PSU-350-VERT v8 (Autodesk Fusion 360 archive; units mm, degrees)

design "PSU-350-VERT" references "MW-LRS-350", "486-1965-ND"
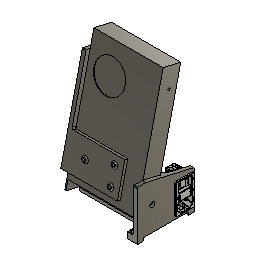
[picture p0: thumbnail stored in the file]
sketch "Sketch3" plane through (0, 0, 0) normal (1, 0, 0) x axis (0, 1, 0)
  line L1 (30.2311, 6) -> (1, 12.7485)
  line L2 (78.5956, 215.4896) -> (30.2311, 6)
  line L3 (49.3645, 222.2381) -> (78.5956, 215.4896)
  line L4 (1, 12.7485) -> (49.3645, 222.2381)
  line L5 (95, 0) -> (0, 0)
  line L6 (25.3624, 40.4789) -> (59.105, 186.6344)
  line L7 (54.4133, 110.7448) -> (42.2337, 113.5567)
  line L8 (91.75, 6) -> (63.75, 6)
  line L9 (91.75, 52.9) -> (91.75, 6)
  line L10 (63.75, 52.9) -> (91.75, 52.9)
  line L11 (63.75, 6) -> (63.75, 52.9)
  line L12 (93, 54.15) -> (93, 4.75)
  line L13 (62.5, 54.15) -> (93, 54.15)
  line L14 (62.5, 4.75) -> (62.5, 54.15)
  line L15 (93, 4.75) -> (62.5, 4.75)
  line L16 (30.2311, 6) -> (63.75, 6)
  line L17 (24.9093, 5.176) -> (25.3593, 7.1248)
  line L18 (0, 0) -> (0, 12.8625)
  line L19 (95, 58.8198) -> (45.0859, 70.3434)
  line L20 (95, 0) -> (95, 58.8198)
  line L21 (36.3889, 6) -> (50.9322, 68.9936)
  line L22 (14.8805, 77.3168) -> (0, 12.8625)
  line L23 (45.0859, 70.3434) -> (14.8805, 77.3168)
  line L24 (61.75, 4) -> (61.75, 6)
  line L25 (95, 4) -> (61.75, 4)
  line L26 (35.0037, 0) -> (36.3889, 6)
  line L27 (48.3889, 0) -> (48.3889, 6)
  line L28 (24.9093, 0) -> (24.9093, 5.176)
  line L29 (35.0037, -5) -> (35.0037, 0)
  line L30 (48.3889, -5) -> (35.0037, -5)
  line L31 (48.3889, 0) -> (48.3889, -5)
  line L32 (0, -5) -> (0, 0)
  line L33 (10, -5) -> (0, -5)
  line L34 (10, 0) -> (10, -5)
  line L35 (95, -5) -> (95, 0)
  line L36 (85, -5) -> (95, -5)
  line L37 (85, 0) -> (85, -5)
  line L38 (10, 6) -> (10, 0)
  line L39 (0, 6) -> (10, 6)
  line L40 (94, 55.15) -> (94, 4)
  line L41 (61.75, 55.15) -> (94, 55.15)
  line L42 (61.75, 6) -> (61.75, 55.15)
  line L43 (85, 4) -> (85, 0)
  line L44 (0, 77.3168) -> (0, 12.8625)
  line L45 (14.8805, 77.3168) -> (0, 77.3168)
  circle C1 centre (25.3624, 40.4789) radius 2.125
  circle C2 centre (59.105, 186.6344) radius 2.125
  point P1 (0, 0)
  point P6 (0, 0)
  point P9 (59.105, 186.6344)
  point P10 (59.105, 186.6344)
  point P8 (25.3624, 40.4789)
  point P11 (25.3624, 40.4789)
  point P12 (42.2337, 113.5567)
  point P13 (54.4133, 110.7448)
  point P3 (30.2311, 6)
  point P22 (25.3593, 7.1248)
  point P24 (0, 0)
  point P25 (45.0859, 70.3434)
  point P27 (50.9322, 68.9936)
  point P28 (36.3889, 6)
  point P31 (45.0859, 70.3434)
  point P32 (61.75, 6)
  point P34 (95, 4)
  point P35 (35.0037, 0)
  point P36 (48.3889, 6)
  point P37 (48.3889, 0)
  point P38 (24.9093, 0)
  point P41 (48.3889, 0)
  point P44 (10, 0)
  point P47 (85, 0)
  point P40 (48.3889, -5)
  point P39 (35.0037, -5)
  point P49 (0, 6)
  point P50 (94, 4)
  point P53 (61.75, 6)
  point P54 (85, 4)
  point P30 (14.8805, 77.3168)
  point P56 (14.8805, 77.3168)
  point P4 (78.5956, 215.4896)
  point P5 (49.3645, 222.2381)
  point P2 (1, 12.7485)
  point P7 (95, 0)
  point P16 (91.75, 52.9)
  point P17 (63.75, 52.9)
  point P15 (91.75, 6)
  point P19 (93, 54.15)
  point P14 (63.75, 6)
  point P23 (24.9093, 5.176)
  point P42 (0, -5)
  point P43 (10, -5)
  point P45 (95, -5)
  point P46 (85, -5)
  perpendicular L1 L2
  parallel L1 L3
  parallel L2 L4
  coincident P1 P6
  horizontal L5
  coincident P9 P10
  coincident P8 P11
  parallel L2 L6
  equal C1 C2
  midpoint L6 P12
  coincident L2 P13
  perpendicular L2 L7
  midpoint L2 P13
  perpendicular L8 L9
  parallel L8 L10
  parallel L9 L11
  horizontal L8
  coincident P3 L8
  coincident L1 P22
  perpendicular L1 L17
  coincident L5 P24
  perpendicular L5 L18
  coincident P1 P24
  coincident L2 P25
  perpendicular L2 L19
  vertical L20
  coincident L19 P27
  coincident L16 P28
  perpendicular L19 L21
  parallel L4 L22
  perpendicular L6 L23
  coincident P25 P31
  coincident L16 P32
  perpendicular L16 L24
  coincident L20 P34
  perpendicular L24 L25
  coincident L5 P35
  parallel L21 L26
  coincident L16 P36
  coincident L5 P37
  perpendicular L5 L27
  coincident L5 P38
  perpendicular L5 L28
  perpendicular L5 L29
  perpendicular L29 L30
  perpendicular L30 L31
  coincident P37 P41
  perpendicular L5 L32
  perpendicular L32 L33
  coincident L5 P44
  perpendicular L5 L34
  perpendicular L5 L35
  coincident L5 P47
  perpendicular L5 L37
  coincident P40 L36
  coincident P39 L33
  horizontal L36
  perpendicular L5 L38
  coincident L18 P49
  perpendicular L18 L39
  coincident P28 L39
  coincident L25 P50
  perpendicular L13 L40
  perpendicular L12 L41
  perpendicular L41 L42
  coincident P32 P53
  coincident L25 P54
  perpendicular L25 L43
  parallel L18 L44
  perpendicular L44 L45
  coincident P30 P56
  dimension "d3" distance P4 P5 = 30
  dimension "d4" distance P2 P5 = 215
  dimension "d5" distance P6 P7 = 95
  dimension "d6" angle L2 L5 = 77
  dimension "d7" diameter C2 = 4.25
  dimension "d8" distance L2 L6 = 12.5
  dimension "d9" distance P10 P11 = 150
  dimension "d10" distance P16 P17 = 28
  dimension "d11" distance P15 P16 = 46.9
  dimension "d12" = 1.25
  dimension "d13" = 30
  dimension "d15" distance P7 P15 = 6
  dimension "d16" distance P7 L12 = 2
  dimension "d17" distance P3 L17 = 5
  dimension "d18" distance P19 L19 = 5
  dimension "d19" distance P25 L21 = 6
  dimension "d20" distance P2 L18 = 1
  dimension "d21" distance L4 L22 = 1
  dimension "d22" distance P15 L25 = 2
  dimension "d23" distance P14 L24 = 2
  dimension "d31" distance P28 L27 = 12
  dimension "d32" distance L1 P23 = 2
  dimension "d33" distance P36 L30 = 11
  dimension "d34" distance P42 P43 = 10
  dimension "d35" distance P45 P46 = 10
  dimension "d72" distance P19 L41 = 1
  dimension "d73" distance L12 L40 = 1
extrude "Extrude1" new body sketch "Sketch3" profile of L1 L2 L4 L5 C1 L8 L9 L10 L11 L16 L17 L18 L19 L20 L21 L22 L23 L24 L25 against normal blind 2
extrude "Extrude2" add sketch "Sketch3" profile of L1 L2 L4 L5 C1 L16 L17 L18 L19 L20 L21 L22 L23 L24 L25 L26 L27 L28 L32 L33 L34 L35 L36 L37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 against normal blind 6
extrude "Extrude3" sketch "Sketch3" profile of L1 L2 L5 L16 L17 L19 L21 L26 L28 blind -10
extrude "Extrude4" sketch "Sketch3" profile of L1 L2 L5 L16 L17 L19 L21 L26 L27 L28 blind -115
extrude "Extrude5" add sketch "Sketch3" profile of L5 L20 L25 L35 L36 L37 L43 against normal blind 10
extrude "Extrude6" sketch "Sketch3" profile of L5 L29 L30 L31 blind 10
chamfer "Chamfer1" distance 5
extrude "Extrude7" sketch "Sketch3" profile of L5 L18 L32 L33 L34 L38 L39 blind -10
sketch "Sketch4" plane through (0, 0, -5) normal (0, 0, -1) x axis (1, 0, 0)
  line L1 (-121, -48.3889) -> (-121, -35.0037)
  line L2 (-111, -48.3889) -> (-121, -48.3889)
  line L3 (-111, -35.0037) -> (-111, -48.3889)
  line L4 (-121, -35.0037) -> (-111, -35.0037)
  line L5 (-120.0415, -41.6963) -> (-118.0207, -38.1963)
  line L6 (-118.0207, -45.1963) -> (-120.0415, -41.6963)
  line L7 (-113.9793, -45.1963) -> (-118.0207, -45.1963)
  line L8 (-111.9585, -41.6963) -> (-113.9793, -45.1963)
  line L9 (-113.9793, -38.1963) -> (-111.9585, -41.6963)
  line L10 (-118.0207, -38.1963) -> (-113.9793, -38.1963)
  line L11 (-9.0415, -90) -> (-7.0207, -86.5)
  line L12 (-7.0207, -86.5) -> (-2.9793, -86.5)
  line L13 (-7.0207, -93.5) -> (-9.0415, -90)
  line L14 (-0.9585, -90) -> (-2.9793, -93.5)
  line L15 (-2.9793, -86.5) -> (-0.9585, -90)
  line L16 (-2.9793, -93.5) -> (-7.0207, -93.5)
  line L17 (-15.0415, -5) -> (-13.0207, -1.5)
  line L18 (-13.0207, -1.5) -> (-8.9793, -1.5)
  line L19 (-13.0207, -8.5) -> (-15.0415, -5)
  line L20 (-6.9585, -5) -> (-8.9793, -8.5)
  line L21 (-8.9793, -1.5) -> (-6.9585, -5)
  line L22 (-8.9793, -8.5) -> (-13.0207, -8.5)
  line L23 (-16, 0) -> (0, 0)
  line L24 (-16, -10) -> (-16, 0)
  line L25 (0, -10) -> (-16, -10)
  line L26 (0, -85) -> (0, -95)
  line L27 (-10, -85) -> (0, -85)
  line L28 (-10, -95) -> (-10, -85)
  line L29 (0, -95) -> (-10, -95)
  line L30 (-111, -35.0037) -> (-121, -48.3889)
  line L31 (-16, 0) -> (-6, -10)
  line L32 (0, -85) -> (-10, -95)
  line L33 (0, 0) -> (0, -10)
  line L34 (-6, 0) -> (-6, -10)
  circle C1 centre (-116, -41.6963) radius 2.25
  circle C2 centre (-5, -90) radius 2.25
  circle C3 centre (-11, -5) radius 2.25
  point P6 (-116, -41.6963)
  point P13 (-116, -41.6963)
  point P14 (-5, -90)
  point P18 (-5, -90)
  point P22 (-11, -5)
  point P26 (-11, -5)
  point P3 (-121, -48.3889)
  point P38 (-121, -48.3889)
  point P5 (-111, -35.0037)
  point P39 (-111, -35.0037)
  point P32 (-16, 0)
  point P40 (-16, 0)
  point P37 (-10, -95)
  point P41 (-10, -95)
  point P35 (0, -85)
  point P42 (0, -85)
  point P43 (-6, -10)
  point P45 (-6, -10)
  point P9 (-118.0207, -45.1963)
  point P21 (-7.0207, -93.5)
  point P29 (-13.0207, -8.5)
  coincident P6 P13
  horizontal L10
  coincident P14 P18
  horizontal L12
  coincident P22 P26
  horizontal L18
  coincident P3 P38
  coincident P5 P39
  midpoint P6 L30
  coincident P32 P40
  midpoint P26 L31
  coincident P37 P41
  coincident P35 P42
  midpoint P14 L32
  coincident P43 P45
  dimension "d49" distance P9 L10 = 7
  dimension "d50" diameter C1 = 4.5
  dimension "d51" distance P21 L12 = 7
  dimension "d52" diameter C2 = 4.5
  dimension "d53" distance P29 L18 = 7
  dimension "d54" diameter C3 = 4.5
extrude "Extrude8" cut sketch "Sketch4" profile of C1 C2 C3 against normal blind 12
extrude "Extrude9" cut sketch "Sketch4" profile of C1 L5 L6 L7 L8 L9 L10 C2 L11 L12 L13 L14 L15 L16 C3 L17 L18 L19 L20 L21 L22 blind -12 from offset -3
extrude "Extrude10" cut sketch "Sketch3" profile of C1 to an object
sketch "Sketch5" plane through (0, 27.3862, -6.3226) normal (0, -0.9744, 0.225) x axis (1, 0, 0)
  line L1 (-6, 78.6826) -> (-6, 12.6467)
  line L2 (-121, 78.6826) -> (-6, 78.6826)
  line L3 (-121, 12.6467) -> (-121, 78.6826)
  line L4 (-6, 12.6467) -> (-121, 12.6467)
  line L5 (-88.5, 45.1467) -> (-38.5, 45.1467)
  circle C1 centre (-88.5, 45.1467) radius 2.125
  circle C2 centre (-38.5, 45.1467) radius 2.125
  point P7 (-88.5, 45.1467)
  point P8 (-88.5, 45.1467)
  point P6 (-38.5, 45.1467)
  point P9 (-38.5, 45.1467)
  point P10 (0, 45.1467)
  horizontal L5
  coincident P7 P8
  coincident P6 P9
  coincident L5 P10
  equal C1 C2
  dimension "d78" distance P6 P7 = 50
  dimension "d79" distance L1 P9 = 32.5
  dimension "d80" diameter C1 = 4.25
extrude "Extrude11" cut sketch "Sketch5" profile of C1 C2 to an object
fillet "Fillet16" radius 1
fillet "Fillet17" radius 1
fillet "Fillet18" radius 5
fillet "Fillet19" radius 2
fillet "Fillet20" radius 5
fillet "Fillet21" radius 3
fillet "Fillet22" radius 3
chamfer "Chamfer5" distance 0.5
chamfer "Chamfer4" distance 2
fillet "Fillet23" radius 1
component_insert "Component Insert2"
joint "Assemble1" OffsetX 0 OffsetY 0 OffsetZ 0 AngleZ 0 alignAngle 257 alignOffsetX 0 alignOffsetY 0 alignOffsetZ 0
component_insert "Component Insert3"
joint "Assemble2" OffsetX 0 OffsetY 0 OffsetZ 0 AngleZ 0 alignAngle 0 alignOffsetX 0 alignOffsetY 0.1 alignOffsetZ 0
sketch "Sketch6" plane through (0, 0, 0) normal (1, 0, 0) x axis (0, 1, 0)
  line L1 (1, 12.7485) -> (49.3645, 222.2381)
  line L2 (17.6097, 93.584) -> (5.2374, 39.9936)
  line L3 (0.3656, 41.1184) -> (5.2374, 39.9936)
  line L4 (12.7379, 94.7087) -> (0.3656, 41.1184)
  line L5 (17.6097, 93.584) -> (12.7379, 94.7087)
  line L6 (29.1095, 34.4823) -> (5.2374, 39.9936)
  line L7 (65.1016, 190.3815) -> (29.1095, 34.4823)
  line L8 (36.3577, 197.0176) -> (65.1016, 190.3815)
  line L9 (12.7379, 94.7087) -> (36.3577, 197.0176)
  line L10 (44.6759, 179.7026) -> (61.7274, 175.766)
  line L11 (15.4323, 53.0345) -> (44.6759, 179.7026)
  line L12 (32.4837, 49.0979) -> (15.4323, 53.0345)
  circle C1 centre (59.105, 186.6344) radius 2.125
  circle C2 centre (25.3624, 40.4789) radius 2.125
  point P7 (17.6097, 93.584)
  point P10 (17.6097, 93.584)
  point P9 (12.7379, 94.7087)
  point P14 (12.7379, 94.7087)
  point P15 (61.7274, 175.766)
  point P18 (32.4837, 49.0979)
  point P6 (5.2374, 39.9936)
  point P5 (25.3624, 40.4789)
  point P2 (59.105, 186.6344)
  point P3 (49.3645, 222.2381)
  parallel L1 L2
  perpendicular L2 L3
  perpendicular L3 L4
  perpendicular L2 L5
  coincident P7 P10
  perpendicular L1 L6
  perpendicular L6 L7
  perpendicular L1 L8
  perpendicular L8 L9
  coincident P9 P14
  coincident L7 P15
  perpendicular L7 L10
  perpendicular L10 L11
  coincident L7 P18
  perpendicular L7 L12
  dimension "d119" distance L1 L2 = 2
  dimension "d120" distance P6 P7 = 55 (= "47 mm + 8 mm")
  dimension "d121" distance P9 P10 = 5
  dimension "d122" distance P5 L6 = 5
  dimension "d123" distance P5 L7 = 5
  dimension "d124" distance P2 L8 = 5
  dimension "d125" distance P5 L12 = 10
  dimension "d126" distance P3 L11 = 5
  dimension "d127" distance P2 L10 = 10
extrude "Extrude12" sketch "Sketch6" blind -6
extrude "Extrude13" sketch "Sketch6" profile of L2 L3 L4 L5 blind 88
sketch "Sketch7" plane through (0, -3.7936, 0.8758) normal (0, 0.9744, -0.225) x axis (-1, 0, 0)
  line L1 (121, 95.1467) -> (121, 40.1467)
  line L2 (33, 95.1467) -> (121, 95.1467)
  line L3 (33, 40.1467) -> (33, 95.1467)
  line L4 (121, 40.1467) -> (33, 40.1467)
  line L5 (96.1754, 67.6467) -> (94.5877, 64.8967)
  line L6 (94.5877, 70.3967) -> (96.1754, 67.6467)
  line L7 (91.4123, 70.3967) -> (94.5877, 70.3967)
  line L8 (89.8246, 67.6467) -> (91.4123, 70.3967)
  line L9 (91.4123, 64.8967) -> (89.8246, 67.6467)
  line L10 (94.5877, 64.8967) -> (91.4123, 64.8967)
  line L11 (48.5877, 55.3967) -> (50.1754, 52.6467)
  line L12 (43.8246, 52.6467) -> (45.4123, 55.3967)
  line L13 (45.4123, 49.8967) -> (43.8246, 52.6467)
  line L14 (48.5877, 49.8967) -> (45.4123, 49.8967)
  line L15 (50.1754, 52.6467) -> (48.5877, 49.8967)
  line L16 (45.4123, 55.3967) -> (48.5877, 55.3967)
  line L17 (48.5877, 84.3967) -> (50.1754, 81.6467)
  line L18 (43.8246, 81.6467) -> (45.4123, 84.3967)
  line L19 (45.4123, 78.8967) -> (43.8246, 81.6467)
  line L20 (48.5877, 78.8967) -> (45.4123, 78.8967)
  line L21 (50.1754, 81.6467) -> (48.5877, 78.8967)
  line L22 (45.4123, 84.3967) -> (48.5877, 84.3967)
  line L23 (47, 81.6467) -> (47, 52.6467)
  circle C1 centre (93, 67.6467) radius 1.75
  circle C2 centre (47, 52.6467) radius 1.75
  circle C3 centre (47, 81.6467) radius 1.75
  circle C4 centre (93, 67.6467) radius 3.25
  circle C5 centre (47, 81.6467) radius 3.25
  circle C6 centre (47, 52.6467) radius 3.25
  point P6 (93, 67.6467)
  point P13 (93, 67.6467)
  point P17 (47, 52.6467)
  point P21 (47, 52.6467)
  point P25 (47, 81.6467)
  point P29 (47, 81.6467)
  point P30 (47, 52.6467)
  point P31 (47, 81.6467)
  point P32 (93, 67.6467)
  point P33 (47, 81.6467)
  point P34 (47, 52.6467)
  point P10 (91.4123, 70.3967)
  point P19 (45.4123, 55.3967)
  point P27 (45.4123, 84.3967)
  coincident P6 P13
  horizontal L7
  coincident P17 P21
  horizontal L16
  coincident P25 P29
  horizontal L22
  coincident P17 P30
  perpendicular L16 L23
  coincident P29 P31
  coincident P13 P32
  coincident P31 P33
  coincident P30 P34
  equal C4 C5
  equal C4 C6
  dimension "d134" distance P10 L10 = 5.5
  dimension "d135" diameter C1 = 3.5
  dimension "d136" distance P19 L14 = 5.5
  dimension "d137" diameter C2 = 3.5
  dimension "d138" distance P27 L20 = 5.5
  dimension "d139" diameter C3 = 3.5
  dimension "d140" distance L1 P21 = 74
  dimension "d142" distance L4 P21 = 12.5
  dimension "d143" distance L4 P29 = 41.5
  dimension "d144" distance L4 P13 = 27.5
  dimension "d145" distance L1 P6 = 28
  dimension "d154" diameter C4 = 6.5
extrude "Extrude14" cut sketch "Sketch7" profile of C1 C2 C3 to an object
extrude "Extrude15" cut sketch "Sketch7" profile of C1 L5 L6 L7 L8 L9 L10 L11 L12 L13 C2 L14 L15 L16 L17 L18 L19 C3 L20 L21 L22 to an object offset 2
chamfer "Chamfer6" distance 0.5
fillet "Fillet24" radius 4
fillet "Fillet25" radius 1
fillet "Fillet26" radius 3
extrude "Extrude16" sketch "Sketch7" profile of C1 L5 L6 L7 L8 L9 L10 L11 L12 L13 C2 L14 L15 L16 L17 L18 L19 C3 L20 L21 L22 C4 C5 C6 blind -2
chamfer "Chamfer7" distance 2
chamfer "Chamfer8" distance 2
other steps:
joint_origin "JointOrigin1" OffsetX 0 OffsetY 0 OffsetZ 0 AngleZ 0
joint_origin "JointOrigin2" OffsetX 0 OffsetY 0 OffsetZ 0 AngleZ 0
named bodies: "PSU-350-Base", "PSU-350-Circuit-Clip"

design "MW-LRS-350"
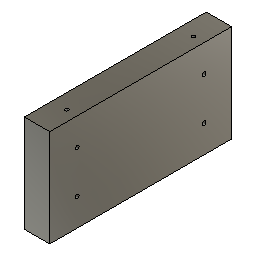
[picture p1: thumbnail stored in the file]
sketch "Sketch1" plane through (0, 0, 0) normal (0, 1, 0) x axis (1, 0, 0)
  line L1 (-33.16, -7.3872) -> (-5.66, -7.3872)
  line L2 (-33.16, -69.3872) -> (-33.16, -7.3872)
  line L3 (-5.66, -69.3872) -> (-33.16, -69.3872)
  line L4 (-5.66, -7.3872) -> (-5.66, -69.3872)
  line L5 (30, 0) -> (0, 0)
  line L6 (30, -115) -> (30, 0)
  line L7 (0, -115) -> (30, -115)
  line L8 (0, 0) -> (0, -115)
  line L9 (-34.61, -0.1) -> (-4.21, -0.1)
  line L10 (-34.61, -76.6744) -> (-34.61, -0.1)
  line L11 (-4.21, -76.6744) -> (-34.61, -76.6744)
  line L12 (-4.21, -0.1) -> (-4.21, -76.6744)
  line L13 (-4.21, -0.1) -> (-34.61, -76.6744)
  line L14 (-5.66, -69.3872) -> (-33.16, -7.3872)
  line L15 (-43.61, 0) -> (0, 0)
  line L16 (-43.61, -76.7744) -> (-43.61, 0)
  line L17 (-4.11, -76.7744) -> (-43.61, -76.7744)
  line L18 (-4.11, -115) -> (-4.11, -76.7744)
  line L19 (0, -115) -> (-4.11, -115)
  line L20 (-34.71, 0) -> (-34.71, -76.7744)
  line L21 (-27.41, -2.9315) -> (-27.41, -7.3872)
  line L22 (-11.41, -2.9315) -> (-27.41, -2.9315)
  line L23 (-11.41, -7.3872) -> (-11.41, -2.9315)
  line L24 (-27.41, -73.8428) -> (-27.41, -69.3872)
  line L25 (-11.41, -73.8428) -> (-27.41, -73.8428)
  line L26 (-11.41, -69.3872) -> (-11.41, -73.8428)
  line L27 (-4.11, 0) -> (-4.11, -76.7744)
  line L28 (42, -6) -> (30, -6)
  line L29 (42, 6) -> (42, -6)
  line L30 (-43.61, 6) -> (42, 6)
  line L31 (-43.61, 0) -> (-43.61, 6)
  line L32 (-5.66, -7.3872) -> (8, -112)
  line L33 (8, -3) -> (8, -112)
  line L34 (30, -3) -> (8, -3)
  point P1 (0, 0)
  point P14 (-19.41, -38.3872)
  point P15 (-19.41, -38.3872)
  point P16 (0, 0)
  point P21 (0, -115)
  point P9 (0, -115)
  point P22 (-34.71, -76.7744)
  point P23 (-34.71, 0)
  point P24 (-27.41, -7.3872)
  point P27 (-11.41, -7.3872)
  point P28 (-27.41, -69.3872)
  point P31 (-11.41, -69.3872)
  point P32 (-4.11, 0)
  point P33 (30, -6)
  point P17 (-43.61, 0)
  point P37 (-43.61, 0)
  point P38 (30, -112)
  point P41 (30, -3)
  point P6 (0, 0)
  point P7 (30, 0)
  point P8 (30, -115)
  point P4 (-33.16, -69.3872)
  point P5 (-5.66, -69.3872)
  point P3 (-33.16, -7.3872)
  point P11 (-34.61, -0.1)
  point P12 (-34.61, -76.6744)
  point P13 (-4.21, -76.6744)
  point P25 (-27.41, -2.9315)
  point P19 (-4.11, -76.7744)
  point P34 (42, -6)
  point P35 (42, 6)
  horizontal L1
  vertical L2
  horizontal L3
  vertical L4
  horizontal L5
  vertical L6
  horizontal L7
  vertical L8
  coincident P1 L8
  coincident P1 L5
  horizontal L9
  vertical L10
  horizontal L11
  vertical L12
  midpoint L13 P14
  midpoint L14 P15
  coincident P14 P15
  coincident P1 P16
  perpendicular L8 L15
  perpendicular L15 L16
  perpendicular L16 L17
  perpendicular L17 L18
  coincident L8 P21
  perpendicular L8 L19
  coincident P9 P21
  coincident L17 P22
  perpendicular L17 L20
  coincident L15 P23
  coincident L1 P24
  perpendicular L1 L21
  perpendicular L21 L22
  coincident L1 P27
  perpendicular L1 L23
  coincident L3 P28
  perpendicular L3 L24
  perpendicular L24 L25
  coincident L3 P31
  perpendicular L3 L26
  coincident P24 L24
  coincident P27 L26
  equal L21 L24
  perpendicular L15 L27
  coincident L15 P32
  coincident L6 P33
  perpendicular L6 L28
  perpendicular L5 L29
  perpendicular L16 L30
  perpendicular L30 L31
  coincident P17 P37
  coincident L6 P38
  perpendicular L6 L32
  perpendicular L32 L33
  coincident L6 P41
  perpendicular L6 L34
  dimension "d1" distance P6 P7 = 30
  dimension "d2" distance P7 P8 = 115
  dimension "d3" distance P4 P5 = 27.5
  dimension "d4" distance P3 P4 = 62
  dimension "d6" distance P11 P12 = 76.5744
  dimension "d7" distance P12 P13 = 30.4
  dimension "d9" distance P1 L9 = 0.1
  dimension "d10" distance P9 L18 = 4.11
  dimension "d11" distance L11 L17 = 0.1
  dimension "d12" distance L10 L16 = 9
  dimension "d13" distance L10 L20 = 0.1
  dimension "d15" distance P24 P25 = 4.4557
  dimension "d16" distance P14 L24 = 8
  dimension "d17" distance P15 L26 = 8 (= "d16")
  dimension "d18" distance L12 P19 = 0.1
  dimension "d42" distance P33 P34 = 12
  dimension "d43" distance L5 L30 = 6
  dimension "d44" distance P34 P35 = 12
  dimension "d214" distance P7 L34 = 3
  dimension "d215" = 3 (= "d214")
  dimension "d216" distance L8 L33 = 8
  dimension "d29" Radius = 3
  dimension "d30" Radius = 1
  dimension "d31" Radius = 1
  dimension "d40" diameter = 4.25
  dimension "d41" distance = 12.5
  dimension "d45" AlongDistance = 25
  dimension "d46" TaperAngle = 0
  dimension "d47" Radius = 1
  dimension "d48" diameter = 6
  dimension "d49" diameter = 15
  dimension "d50" distance = 6
  dimension "d52" distance = 2.54
  dimension "d53" distance = 2.54 (= "d52")
  dimension "d55" distance = 2.54
  dimension "d56" distance = 6
  dimension "d57" AlongDistance = -12
  dimension "d58" TaperAngle = 0
  dimension "d60" diameter = 4.25
  dimension "d61" distance = 0.1
  dimension "d67" Side1Offset = 0
  dimension "d68" TaperAngle = 0
  dimension "d69" AlongDistance = -12
  dimension "d70" TaperAngle = 0
  dimension "d71" AlongDistance = -45
  dimension "d72" TaperAngle = 0
  dimension "d73" AlongDistance = 25
  dimension "d74" TaperAngle = 0
  dimension "d75" distance = 20
  dimension "d76" distance = 20
  dimension "d77" distance = 20
  dimension "d78" distance = 20
  dimension "d79" distance = 15
  dimension "d80" distance = 25
  dimension "d81" distance = 15
  dimension "d82" diameter = 5.4
  dimension "d83" distance = 6.5
  dimension "d84" distance = 6.5
  dimension "d85" distance = 8
  dimension "d86" distance = 6.5
  dimension "d87" distance = 3
  dimension "d88" Side1Offset = 0
  dimension "d89" TaperAngle = 0
  dimension "d90" distance = -0.1
  dimension "d91" distance = -0.1
  dimension "d92" Radius = 1
  dimension "d95" Radius = 2
  dimension "d96" Radius = 1
  dimension "d97" Radius = 2
  dimension "d98" Radius = 2
  dimension "d99" Radius = 2
  dimension "d100" Radius = 2
  dimension "d101" distance = 5
  dimension "d102" distance = 1
  dimension "d103" distance = 1
  dimension "d104" distance = 5
  dimension "d105" AlongDistance = 4
  dimension "d106" TaperAngle = 0
  dimension "d107" AlongDistance = -3
  dimension "d108" TaperAngle = 0
  dimension "d109" leftDistance = 2
  dimension "d110" Radius = 2
  dimension "d111" Radius = 1
  dimension "d112" distance = 1.97
  dimension "d113" distance = 1
  dimension "d114" distance = 1.7
  dimension "d115" distance = 4.4
  dimension "d116" distance = 4.4
  dimension "d117" distance = 4.4 (= "d116")
  dimension "d118" distance = 4.4 (= "d116")
  dimension "d119" distance = 4.4 (= "d116")
  dimension "d120" distance = 4.4 (= "d116")
  dimension "d121" distance = 4.4 (= "d116")
  dimension "d122" distance = 4.4 (= "d116")
  dimension "d123" distance = 4.4 (= "d116")
  dimension "d124" distance = 4.4 (= "d116")
  dimension "d125" Radius = 2
  dimension "d126" distance = 3.25
  dimension "d127" distance = 2.54
  dimension "d128" distance = 2.54 (= "d127")
  dimension "d129" distance = 2.54 (= "d127")
  dimension "d130" distance = 9
  dimension "d131" AlongDistance = -10
  dimension "d132" TaperAngle = 0
  dimension "d133" Radius = 4
  dimension "d134" Radius = 1.5
  dimension "d135" rightDistance = 4
  dimension "d136" distance = 12
  dimension "d137" distance = 0.25
  dimension "d140" Side1Offset = 0.1
  dimension "d141" TaperAngle = 0
  dimension "d145" distance = 55
  dimension "d146" distance = 24
  dimension "d147" diameter = 2.9
  dimension "d148" distance = 5
  dimension "d149" distance = 45
  dimension "d150" distance = 1
  dimension "d151" distance = 15
  dimension "d152" distance = 6
  dimension "d153" distance = 3.37
  dimension "d154" distance = 3.37
  dimension "d155" Side1Offset = 0
  dimension "d156" TaperAngle = 0
  dimension "d157" distance = 0.5
  dimension "d158" ProfileOffset = 0
  dimension "d159" Side1Offset = 0
  dimension "d160" TaperAngle = 0
  dimension "d161" ProfileOffset = 0
  dimension "d162" Side1Offset = 0
  dimension "d163" TaperAngle = 0
  dimension "d164" distance = 6
  dimension "d165" Radius = 3
  dimension "d166" Radius = 1
  dimension "d167" Radius = 1
  dimension "d168" distance = 30
  dimension "d169" distance = 34
  dimension "d176" distance = 22
  dimension "d177" distance = 14
  dimension "d178" distance = 2
  dimension "d179" distance = 2
  dimension "d180" diameter = 2.9
  dimension "d181" distance = 11
  dimension "d182" distance = 1
  dimension "d185" distance = 30
  dimension "d186" distance = 34
  dimension "d187" distance = 22
  dimension "d188" distance = 14
  dimension "d189" distance = 2
  dimension "d190" distance = 2
  dimension "d191" diameter = 2.9
  dimension "d192" distance = 11
  dimension "d193" distance = 1
  dimension "d194" distance = 10
  dimension "d195" distance = 1
  dimension "d196" distance = 1
  dimension "d197" distance = 70
  dimension "d198" distance = 63
  dimension "d199" distance = 28
  dimension "d200" distance = 71
  dimension "d202" distance = 14
  dimension "d203" diameter = 2.9
  dimension "d204" distance = 1
  dimension "d205" distance = 1
  dimension "d206" distance = 40
  dimension "d207" Side1Offset = 0
  dimension "d208" TaperAngle = 0
  dimension "d209" ProfileOffset = 0
  dimension "d210" Side1Offset = 0
  dimension "d211" TaperAngle = 0
  dimension "d212" Side1Offset = 0
  dimension "d213" TaperAngle = 0
extrude "Extrude5" new body sketch "Sketch1" profile of L5 L6 L7 L8 L32 L33 L34 along normal blind 215 Linear Dimension-10 3.37 Linear Dimension-11 3.37
sketch "Sketch2" plane through (0, 0, 0) normal (-1, 0, 0) x axis (0, -1, 0)
  line L1 (0, 115) -> (0, 0)
  line L2 (-215, 115) -> (0, 115)
  line L3 (-215, 0) -> (-215, 115)
  line L4 (0, 0) -> (-215, 0)
  line L5 (-182.5, 32.5) -> (-32.5, 32.5)
  line L6 (-182.5, 82.5) -> (-182.5, 32.5)
  line L7 (-32.5, 82.5) -> (-182.5, 82.5)
  line L8 (-32.5, 32.5) -> (-32.5, 82.5)
  line L9 (-32.5, 32.5) -> (-182.5, 82.5)
  line L10 (-107.5, 0) -> (-107.5, 115)
  line L11 (-200, 113) -> (-215, 113)
  line L12 (-200, 2) -> (-200, 113)
  line L13 (-215, 2) -> (-200, 2)
  curve K1
  circle C1 centre (-182.5, 82.5) radius 2.25
  circle C2 centre (-182.5, 32.5) radius 2.25
  circle C3 centre (-32.5, 32.5) radius 2.25
  circle C4 centre (-32.5, 82.5) radius 2.25
  circle C5 centre (-47.45, 78.3) radius 26
  point P11 (-107.5, 57.5)
  point P10 (-107.5, 57.5)
  point P8 (-182.5, 82.5)
  point P12 (-182.5, 82.5)
  point P7 (-182.5, 32.5)
  point P13 (-182.5, 32.5)
  point P6 (-32.5, 32.5)
  point P14 (-32.5, 32.5)
  point P9 (-32.5, 82.5)
  point P15 (-32.5, 82.5)
  point P16 (-107.5, 115)
  point P17 (-107.5, 0)
  point P19 (-215, 113)
  point P22 (-215, 2)
  point P18 (-47.45, 78.3)
  point P21 (-200, 2)
  horizontal L5
  vertical L6
  horizontal L7
  vertical L8
  midpoint L9 P11
  coincident P10 P11
  coincident P8 P12
  coincident P7 P13
  coincident P6 P14
  coincident P9 P15
  equal C3 C4
  equal C2 C4
  equal C1 C2
  coincident L2 P16
  coincident L4 P17
  perpendicular L4 L10
  midpoint P10 L10
  coincident L3 P19
  perpendicular L3 L11
  perpendicular L11 L12
  perpendicular L12 L13
  coincident L3 P22
  dimension "d34" distance P6 P9 = 50
  dimension "d35" distance P8 P9 = 150
  dimension "d36" diameter C4 = 4.5
  dimension "d220" distance L2 P18 = 36.7
  dimension "d221" distance L1 P18 = 47.45
  dimension "d222" diameter C5 = 52
  dimension "d223" distance L2 L11 = 2
  dimension "d224" distance L4 L13 = 2
  dimension "d225" distance P21 P22 = 15
  dimension "d238" distance L3 P13 = 32.5
extrude "Extrude6" sketch "Sketch2" profile of C1 C2 C3 C4 blind 4
extrude "Extrude26" cut sketch "Sketch2" profile of L3 L11 L12 L13 to an object offset 5
extrude "Extrude27" cut sketch "Sketch2" profile of C4 C5 against normal blind 1
sketch "Sketch10" plane through (0, 0, 115) normal (0, 0, 1) x axis (-1, 0, 0)
  line L1 (-30, 0) -> (0, 0)
  line L2 (-30, -215) -> (-30, 0)
  line L3 (0, -215) -> (-30, -215)
  line L4 (0, 0) -> (0, -215)
  line L5 (-17.5, -32.5) -> (-17.5, -182.5)
  line L6 (-17.5, -32.5) -> (0, -32.5)
  line L7 (-17.5, -182.5) -> (0, -182.5)
  circle C1 centre (-17.5, -32.5) radius 2
  circle C2 centre (-17.5, -182.5) radius 2
  point P7 (-17.5, -182.5)
  point P8 (-17.5, -182.5)
  point P6 (-17.5, -32.5)
  point P9 (-17.5, -32.5)
  point P10 (0, -32.5)
  point P12 (0, -32.5)
  point P11 (0, -182.5)
  point P14 (0, -182.5)
  point P15 (-17.5, -182.5)
  point P13 (-17.5, -32.5)
  coincident P7 P8
  vertical L5
  coincident P6 P9
  equal C1 C2
  coincident P10 P12
  perpendicular L4 L6
  coincident P11 P14
  perpendicular L4 L7
  coincident P7 P15
  coincident P6 P13
  dimension "d231" diameter C2 = 4
  dimension "d232" distance L2 L5 = 12.5
extrude "Extrude28" cut sketch "Sketch10" profile of C1 C2 against normal blind 5
extrude "Extrude29" sketch "Sketch10" profile of C1 C2 blind 5
named bodies: "PSU"

design "486-1965-ND"
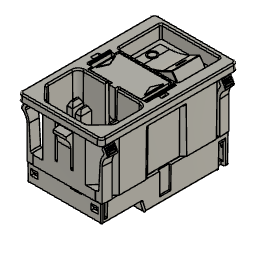
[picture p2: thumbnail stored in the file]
